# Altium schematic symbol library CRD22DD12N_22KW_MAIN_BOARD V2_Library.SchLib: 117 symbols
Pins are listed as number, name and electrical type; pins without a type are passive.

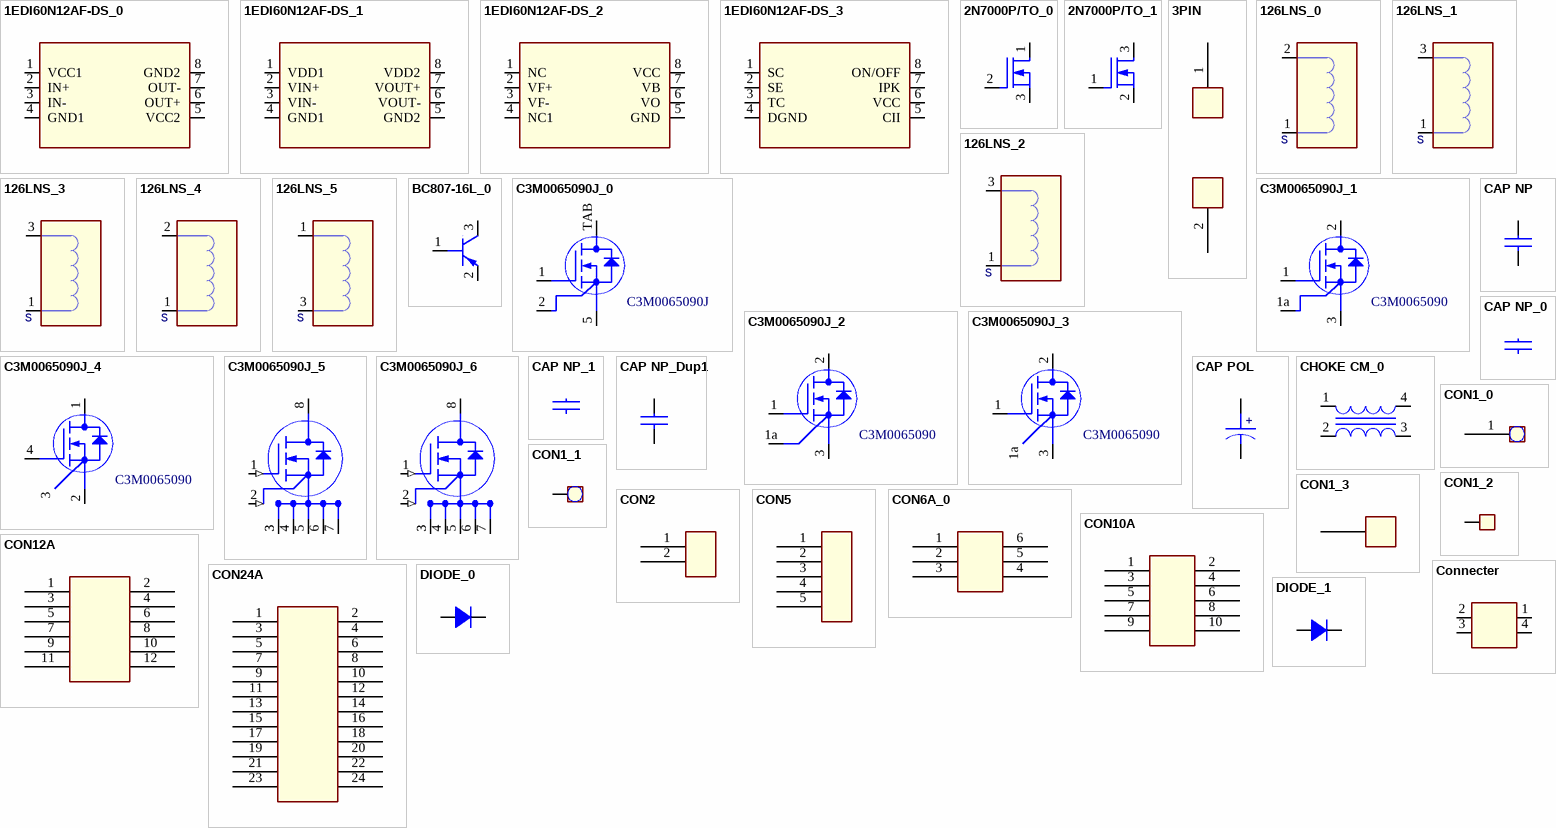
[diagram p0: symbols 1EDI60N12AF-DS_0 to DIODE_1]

## 1EDI60N12AF-DS_0
designator U?
pins: 1 VCC1, 2 IN+, 3 IN-, 4 GND1, 5 VCC2, 6 OUT+, 7 OUT-, 8 GND2

## 1EDI60N12AF-DS_1
designator U?
pins: 1 VDD1, 2 VIN+, 3 VIN-, 4 GND1, 5 GND2, 6 VOUT-, 7 VOUT+, 8 VDD2

## 1EDI60N12AF-DS_2
designator U?
pins: 1 NC, 2 VF+, 3 VF-, 4 NC1, 5 GND, 6 VO, 7 VB, 8 VCC

## 1EDI60N12AF-DS_3
designator U?
pins: 1 SC, 2 SE, 3 TC, 4 DGND, 5 CII, 6 VCC, 7 IPK, 8 ON/OFF

## 2N7000P/TO_0
designator Q?
pins: 1 D, 2 G, 3 S

## 2N7000P/TO_1
designator Q?
pins: 1 G, 2 S, 3 D

## 3PIN
designator CR?
pins: 1, 2

## 126LNS_0
designator L?
pins: 1, 2 3

## 126LNS_1
designator L?
pins: 1, 3

## 126LNS_2
designator L?
pins: 1, 3

## 126LNS_3
designator L?
pins: 1, 3

## 126LNS_4
designator L?
pins: 1, 2

## 126LNS_5
designator L?
pins: 1, 3

## BC807-16L_0
designator Q?
pins: 1 BASE, 2 EMITTER, 3 COLLECTOR

## C3M0065090J_0
designator Q?, comment C3M0065090J
pins: 1 G, 2 DS, 5 S3, TAB D

## C3M0065090J_1
designator Q?, comment C3M0065090
pins: 1 G, 1a DS, 2 D, 3 S

## C3M0065090J_2
designator Q?, comment C3M0065090
pins: 1 G, 1a DS, 2 D, 3 S

## C3M0065090J_3
designator Q?, comment C3M0065090
pins: 1 G, 1a DS, 2 D, 3 S

## C3M0065090J_4
designator Q?, comment C3M0065090
pins: 1 D, 2 S, 3 GS, 4 G

## C3M0065090J_5
designator Q?
pins: 1 GATE (in), 2 GATE RTN (in), 3 SOURCE, 3 SOURCE, 4 SOURCE4, 5 SOURCE5, 6 SOURCE6, 7 SOURCE7, 8 DRAIN

## C3M0065090J_6
designator Q?
pins: 1 GATE (in), 2 GATE RTN (in), 3 SOURCE, 3 SOURCE, 4 SOURCE4, 5 SOURCE5, 6 SOURCE6, 7 SOURCE7, 8 DRAIN

## CAP NP
designator C?
pins: 1, 2

## CAP NP_0
designator C?
pins: 1, 2

## CAP NP_1
designator C?
pins: 1, 2

## CAP NP_Dup1
designator C?
pins: 1, 2

## CAP POL
designator C?
pins: 1, 2

## CHOKE CM_0
designator L?
pins: 1, 2, 3, 4

## CON1_0
designator J?
pins: 1

## CON1_1
designator J?
pins: 1

## CON1_2
designator J?
pins: 1

## CON1_3
designator J?
pins: 1, 2, 3, 4

## CON2
designator J?
pins: 1, 2

## CON5
designator J?
pins: 1, 2, 3, 4, 5

## CON6A_0
designator J?
pins: 1, 2, 3, 4, 5, 6

## CON10A
designator J?
pins: 1, 2, 3, 4, 5, 6, 7, 8, 9, 10

## CON12A
designator J?
pins: 1, 2, 3, 4, 5, 6, 7, 8, 9, 10, 11, 12

## CON24A
designator J?
pins: 1, 2, 3, 4, 5, 6, 7, 8, 9, 10, 11, 12, 13, 14, 15, 16, 17, 18, 19, 20, 21, 22, 23, 24

## Connecter
designator CON?
pins: 1, 2, 3, 4

## DIODE_0
designator D?
pins: 1 A, 2 K

## DIODE_1
designator D?
pins: 1 K, 2 A

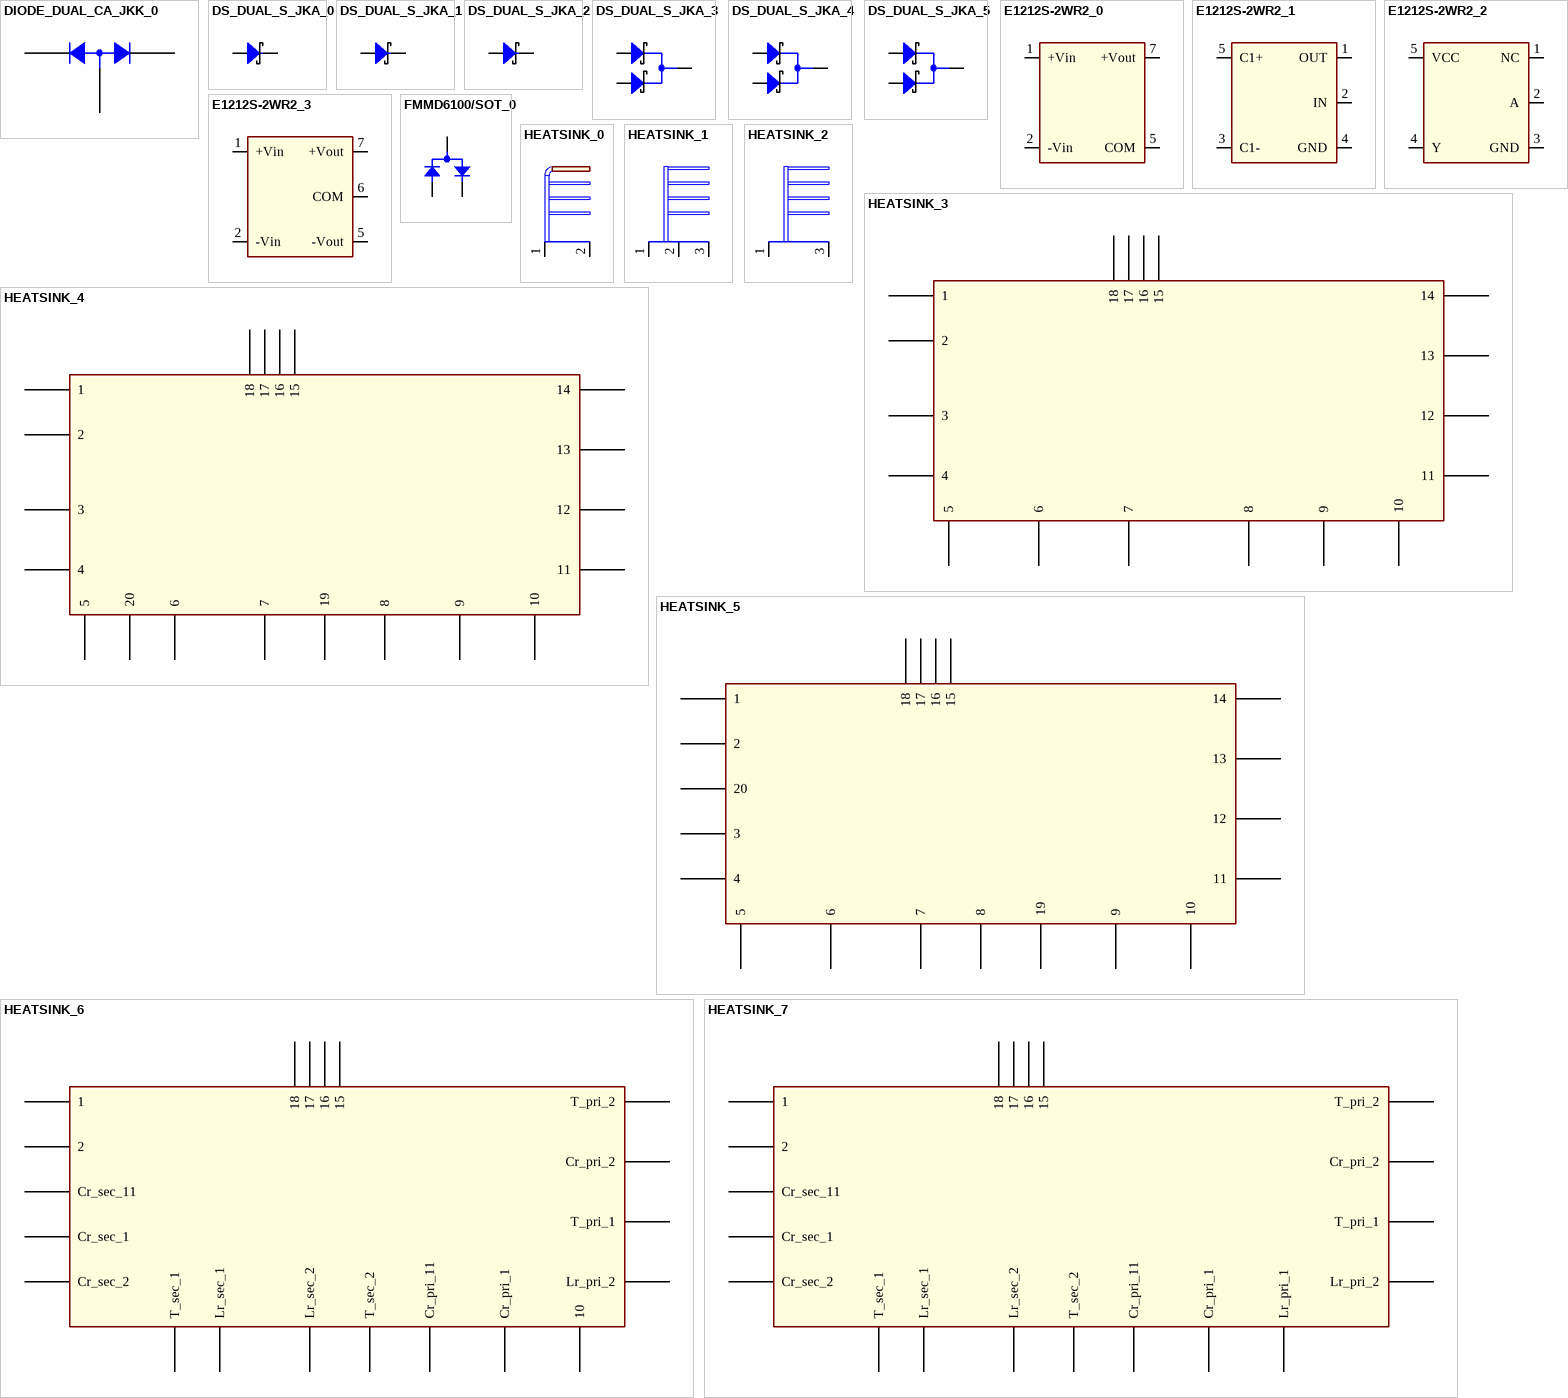
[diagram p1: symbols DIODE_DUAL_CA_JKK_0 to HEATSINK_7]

## DIODE_DUAL_CA_JKK_0
designator DN?
pins: 1 3, 2, 3 1

## DS_DUAL_S_JKA_0
designator DN?
pins: 1, 2

## DS_DUAL_S_JKA_1
designator DN?
pins: 1, 2

## DS_DUAL_S_JKA_2
designator DN?
pins: 1, 2

## DS_DUAL_S_JKA_3
designator DN?
pins: 1, 2, 3

## DS_DUAL_S_JKA_4
designator DN?
pins: 1, 2, 3

## DS_DUAL_S_JKA_5
designator DN?
pins: 1, 2, 3

## E1212S-2WR2_0
designator U?
pins: 1 +Vin, 2 -Vin, 5 COM, 7 +Vout

## E1212S-2WR2_1
designator U?
pins: 1 OUT, 2 IN, 3 C1-, 4 GND, 5 C1+

## E1212S-2WR2_2
designator U?
pins: 1 NC, 2 A, 3 GND, 4 Y, 5 VCC

## E1212S-2WR2_3
designator U?
pins: 1 +Vin, 2 -Vin, 5 -Vout, 6 COM, 7 +Vout

## FMMD6100/SOT_0
designator D?
pins: 1 C1, 2 C2, 3 A

## HEATSINK_0
designator HS?
pins: 1, 2

## HEATSINK_1
designator HS?
pins: 1, 2, 3

## HEATSINK_2
designator HS?
pins: 1, 3

## HEATSINK_3
designator T?
pins: 1, 2, 3, 4, 5, 6, 7, 8, 9, 10, 11, 12, 13, 14, 15, 16, 17, 18

## HEATSINK_4
designator T?
pins: 1, 2, 3, 4, 5, 6, 7, 8, 9, 10, 11, 12, 13, 14, 15, 16, 17, 18, 19, 20

## HEATSINK_5
designator T?
pins: 1, 2, 3, 4, 5, 6, 7, 8, 9, 10, 11, 12, 13, 14, 15, 16, 17, 18, 19, 20

## HEATSINK_6
designator T?
pins: 1, 2, 3 Cr_sec_1, 4 Cr_sec_2, 5 T_sec_1, 6 Lr_sec_1, 7 Lr_sec_2, 8 T_sec_2, 9 Cr_pri_1, 10, 11 Lr_pri_2, 12 T_pri_1, 13 Cr_pri_2, 14 T_pri_2, 15, 16, 17, 18, 19 Cr_pri_11, 20 Cr_sec_11

## HEATSINK_7
designator T?
pins: 1, 2, 3 Cr_sec_1, 4 Cr_sec_2, 5 T_sec_1, 6 Lr_sec_1, 7 Lr_sec_2, 8 T_sec_2, 9 Cr_pri_1, 10 Lr_pri_1, 11 Lr_pri_2, 12 T_pri_1, 13 Cr_pri_2, 14 T_pri_2, 15, 16, 17, 18, 19 Cr_pri_11, 20 Cr_sec_11

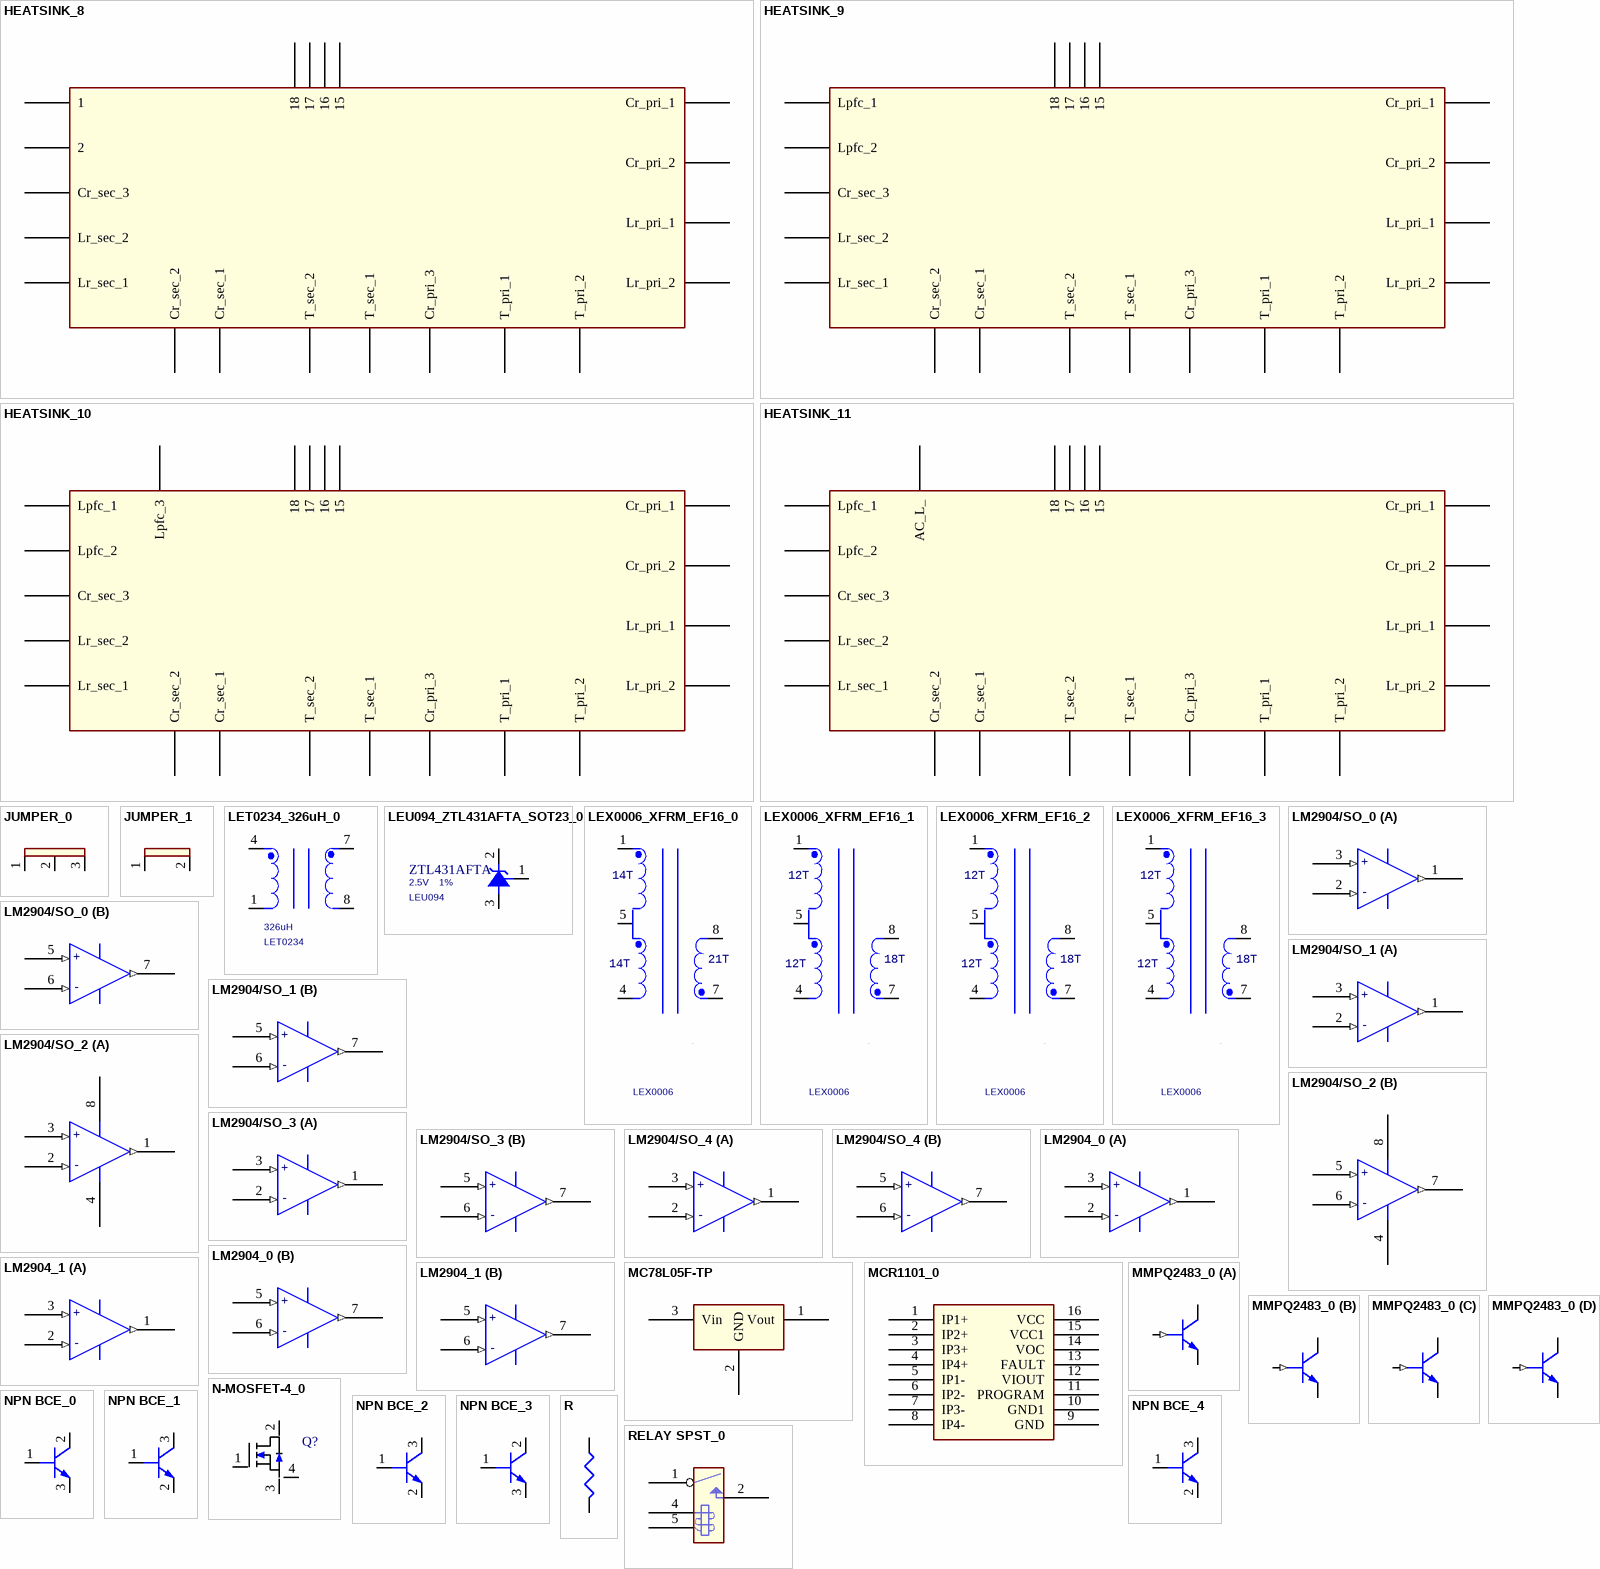
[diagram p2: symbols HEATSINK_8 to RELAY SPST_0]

## HEATSINK_8
designator T?
pins: 1, 2, 3 Lr_sec_2, 4 Lr_sec_1, 5 Cr_sec_2, 6 Cr_sec_1, 7 T_sec_2, 8 T_sec_1, 9 T_pri_1, 10 T_pri_2, 11 Lr_pri_2, 12 Lr_pri_1, 13 Cr_pri_2, 14 Cr_pri_1, 15, 16, 17, 18, 19 Cr_pri_3, 20 Cr_sec_3

## HEATSINK_9
designator T?
pins: 1 Lpfc_1, 2 Lpfc_2, 3 Lr_sec_2, 4 Lr_sec_1, 5 Cr_sec_2, 6 Cr_sec_1, 7 T_sec_2, 8 T_sec_1, 9 T_pri_1, 10 T_pri_2, 11 Lr_pri_2, 12 Lr_pri_1, 13 Cr_pri_2, 14 Cr_pri_1, 15, 16, 17, 18, 19 Cr_pri_3, 20 Cr_sec_3

## HEATSINK_10
designator T?
pins: 1 Lpfc_1, 2 Lpfc_2, 3 Lr_sec_2, 4 Lr_sec_1, 5 Cr_sec_2, 6 Cr_sec_1, 7 T_sec_2, 8 T_sec_1, 9 T_pri_1, 10 T_pri_2, 11 Lr_pri_2, 12 Lr_pri_1, 13 Cr_pri_2, 14 Cr_pri_1, 15, 16, 17, 18, 19 Cr_pri_3, 20 Cr_sec_3, 21 Lpfc_3

## HEATSINK_11
designator T?
pins: 1 Lpfc_1, 2 Lpfc_2, 3 Lr_sec_2, 4 Lr_sec_1, 5 Cr_sec_2, 6 Cr_sec_1, 7 T_sec_2, 8 T_sec_1, 9 T_pri_1, 10 T_pri_2, 11 Lr_pri_2, 12 Lr_pri_1, 13 Cr_pri_2, 14 Cr_pri_1, 15, 16, 17, 18, 19 Cr_pri_3, 20 Cr_sec_3, 21 AC_L_

## JUMPER_0
designator JM?
pins: 1, 2, 3

## JUMPER_1
designator JM?
pins: 1, 2

## LET0234_326uH_0
designator T?, comment 326uH  LLF Part Number: LET0234
footprint IND-LET0234-34x17
pins: 1, 4, 7, 8

## LEU094_ZTL431AFTA_SOT23_0
designator U?, comment ZTL431AFTA  VREF: 2.5V  Tolerance: 1%  LLF Part Number: LEU094
footprint SOT23_1-32
pins: 1 REF, 2 K, 3 A

## LEX0006_XFRM_EF16_0
designator T?, comment LLF Part Number: LEX0006  (hidden comment: 8.5mH)
NC: 2,3,5,6,7
footprint XFMR-EF16-v
pins: 1, 4, 5, 7, 8

## LEX0006_XFRM_EF16_1
designator T?, comment LLF Part Number: LEX0006  (hidden comment: 8.5mH)
NC: 2,3,5,6,7
footprint XFMR-EF16-v
pins: 1, 4, 5, 7, 8

## LEX0006_XFRM_EF16_2
designator T?, comment LLF Part Number: LEX0006  (hidden comment: 8.5mH)
NC: 2,3,5,6,7
footprint XFMR-EF16-v
pins: 1, 4, 5, 7, 8

## LEX0006_XFRM_EF16_3
designator T?, comment LLF Part Number: LEX0006  (hidden comment: 8.5mH)
footprint XFMR-EF16-v
pins: 1, 4, 5, 7, 8

## LM2904/SO_0
designator U?
part A pins: 1 OUT (out), 2 -IN (in), 3 +IN (in)
part B pins: 5 +IN (in), 6 -IN (in), 7 OUT (out)

## LM2904/SO_1
designator U?
part A pins: 1 OUT (out), 2 -IN (in), 3 +IN (in)
part B pins: 5 +IN (in), 6 -IN (in), 7 OUT (out)

## LM2904/SO_2
designator U?
part A pins: 1 OUT (out), 2 -IN (in), 3 +IN (in), 4 V- (power), 8 V+ (power)
part B pins: 4 V- (power), 5 +IN (in), 6 -IN (in), 7 OUT (out), 8 V+ (power)

## LM2904/SO_3
designator U?
part A pins: 1 OUT (out), 2 -IN (in), 3 +IN (in), 4 V- (power) hidden, 8 V+ (power) hidden
part B pins: 4 V- (power) hidden, 5 +IN (in), 6 -IN (in), 7 OUT (out), 8 V+ (power) hidden

## LM2904/SO_4
designator U?
part A pins: 1 OUT (out), 2 -IN (in), 3 +IN (in), 4 V- (power) hidden, 8 V+ (power) hidden
part B pins: 4 V- (power) hidden, 5 +IN (in), 6 -IN (in), 7 OUT (out), 8 V+ (power) hidden

## LM2904_0
designator U?
part A pins: 1 OUT (out), 2 -IN (in), 3 +IN (in)
part B pins: 5 +IN (in), 6 -IN (in), 7 OUT (out)

## LM2904_1
designator U?
part A pins: 1 OUT (out), 2 -IN (in), 3 +IN (in), 4 V- (power) hidden, 8 V+ (power) hidden
part B pins: 4 V- (power) hidden, 5 +IN (in), 6 -IN (in), 7 OUT (out), 8 V+ (power) hidden

## MC78L05F-TP
designator U?
pins: 1 Vout, 2 GND, 3 Vin

## MCR1101_0
designator U?
pins: 1 IP1+, 2 IP2+, 3 IP3+, 4 IP4+, 5 IP1-, 6 IP2-, 7 IP3-, 8 IP4-, 9 GND, 10 GND1, 11 PROGRAM, 12 VIOUT, 13 FAULT, 14 VOC, 15 VCC1, 16 VCC

## MMPQ2483_0
designator Q?
part A pins: 1 B (in), 2 E, 3 C
part B pins: 5 E, 6 B (in), 7 C
part C pins: 8 C, 9 B (in), 10 E
part D pins: 12 E, 13 B (in), 14 C

## N-MOSFET-4_0
designator Q?  (value not drawn)
footprint TO-247-4
pins: 1 G, 2 D, 3 S1, 4 S

## NPN BCE_0
designator Q?
PspiceTemplate: Q^@REFDES %C %B %E
simulation model NPN BCE_0
pins: 1 B, 2 C, 3 E

## NPN BCE_1
designator Q?
PspiceTemplate: Q^@REFDES %C %B %E
simulation model NPN BCE_1
pins: 1 B, 2 E, 3 C

## NPN BCE_2
designator Q?
PspiceTemplate: Q^@REFDES %C %B %E
simulation model NPN BCE_2
pins: 1 B, 2 E, 3 C

## NPN BCE_3
designator Q?
PspiceTemplate: Q^@REFDES %C %B %E
simulation model NPN BCE_3
pins: 1 B, 2 C, 3 E

## NPN BCE_4
designator Q?
PspiceTemplate: Q^@REFDES %C %B %E
simulation model NPN BCE_4
pins: 1 B, 2 E, 3 C

## R
designator R?
pins: 1, 2

## RELAY SPST_0
designator RL?
pins: 1 COMMON, 2 NO, 4 COIL1, 5 COIL2

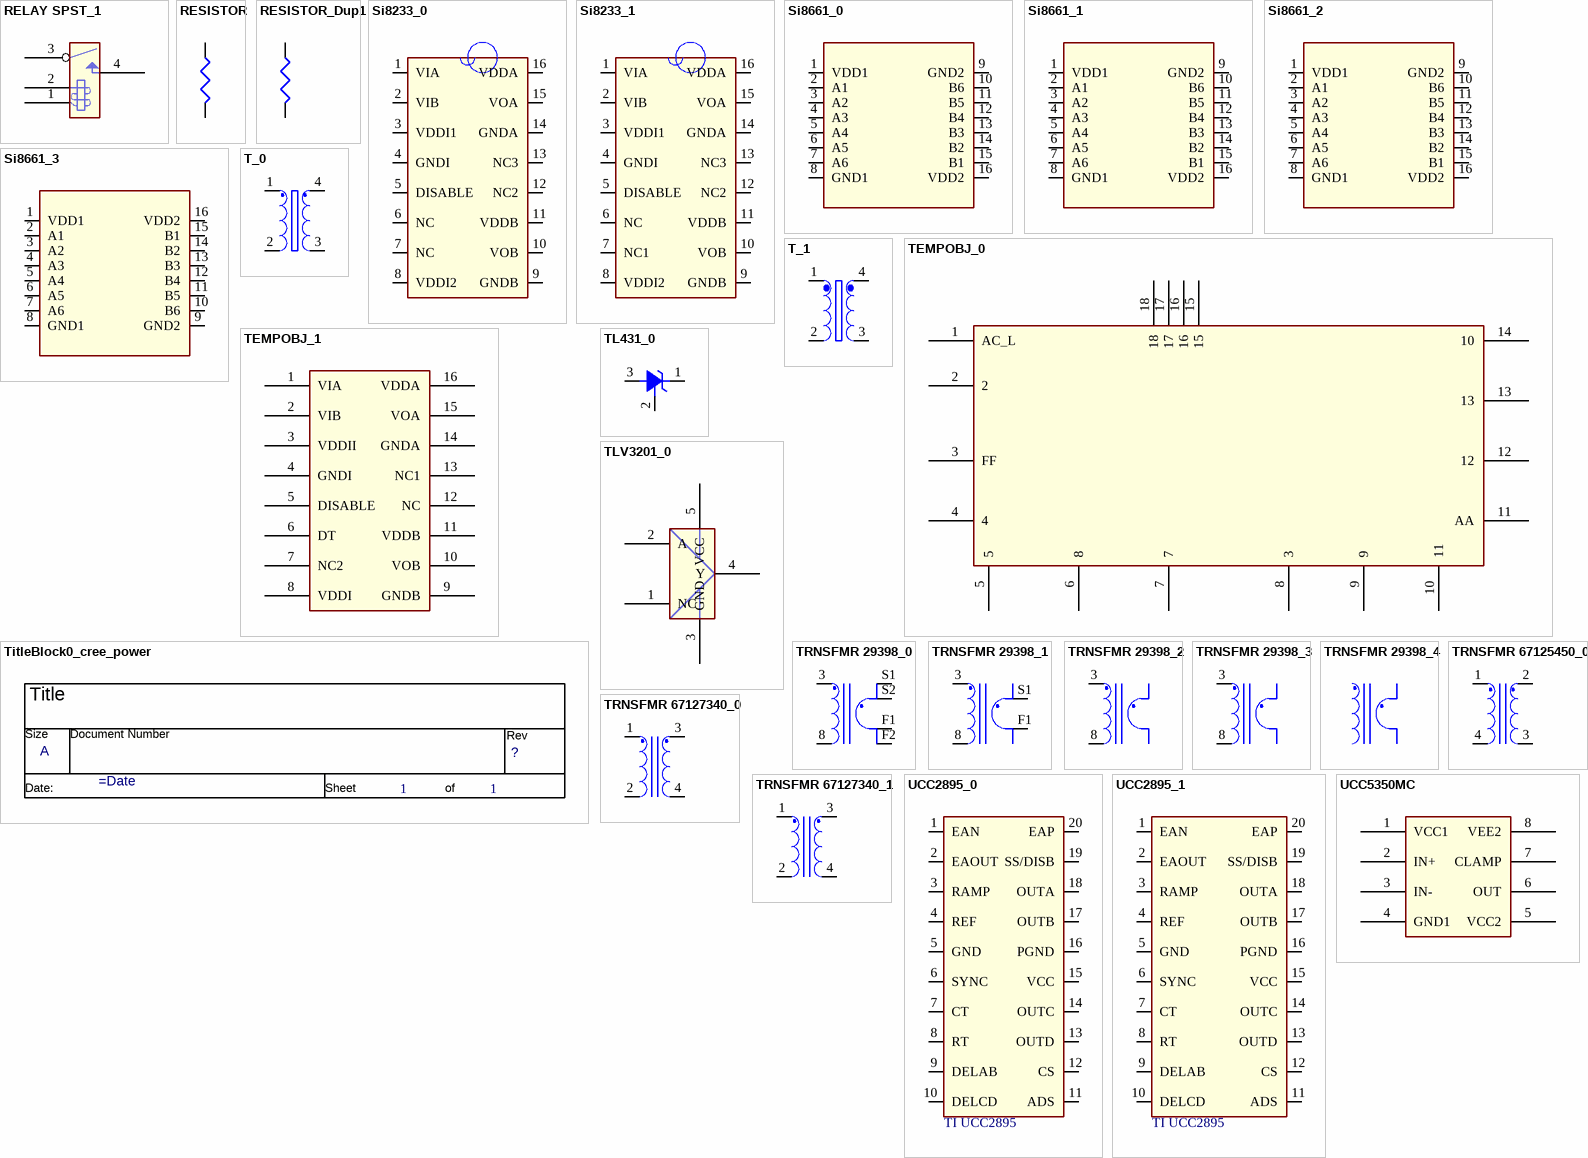
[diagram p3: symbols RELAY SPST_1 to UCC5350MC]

## RELAY SPST_1
designator RL?
pins: 1 COIL2, 2 COIL1, 3 COMMON, 4 NO

## RESISTOR
designator R?
pins: 1, 2

## RESISTOR_Dup1
designator R?
pins: 1, 2

## Si8233_0
designator U?
pins: 1 VIA, 2 VIB, 3 VDDI1, 4 GNDI, 5 DISABLE, 6 NC, 7 NC, 8 VDDI2, 9 GNDB, 10 VOB, 11 VDDB, 12 NC2, 13 NC3, 14 GNDA, 15 VOA, 16 VDDA

## Si8233_1
designator U?
pins: 1 VIA, 2 VIB, 3 VDDI1, 4 GNDI, 5 DISABLE, 6 NC, 7 NC1, 8 VDDI2, 9 GNDB, 10 VOB, 11 VDDB, 12 NC2, 13 NC3, 14 GNDA, 15 VOA, 16 VDDA

## Si8661_0
designator U?
pins: 1 VDD1, 2 A1, 3 A2, 4 A3, 5 A4, 6 A5, 7 A6, 8 GND1, 9 GND2, 10 B6, 11 B5, 12 B4, 13 B3, 14 B2, 15 B1, 16 VDD2

## Si8661_1
designator U?
pins: 1 VDD1, 2 A1, 3 A2, 4 A3, 5 A4, 6 A5, 7 A6, 8 GND1, 9 GND2, 10 B6, 11 B5, 12 B4, 13 B3, 14 B2, 15 B1, 16 VDD2

## Si8661_2
designator U?
pins: 1 VDD1, 2 A1, 3 A2, 4 A3, 5 A4, 6 A5, 7 A6, 8 GND1, 9 GND2, 10 B6, 11 B5, 12 B4, 13 B3, 14 B2, 15 B1, 16 VDD2

## Si8661_3
designator U?
pins: 1 VDD1, 2 A1, 3 A2, 4 A3, 5 A4, 6 A5, 7 A6, 8 GND1, 9 GND2, 10 B6, 11 B5, 12 B4, 13 B3, 14 B2, 15 B1, 16 VDD2

## T_0
designator T?
pins: 1, 2, 3, 4

## T_1
designator T?
pins: 1, 2, 3, 4

## TEMPOBJ_0
designator T?
pins: 1 AC_L, 2, 3 FF, 4, 5, 6 8, 7, 8 3, 9, 10 11, 11 AA, 12, 13, 14 10, 15, 16, 17, 18

## TEMPOBJ_1
designator U?
pins: 1 VIA, 2 VIB, 3 VDDII, 4 GNDI, 5 DISABLE, 6 DT, 7 NC2, 8 VDDI, 9 GNDB, 10 VOB, 11 VDDB, 12 NC, 13 NC1, 14 GNDA, 15 VOA, 16 VDDA

## TitleBlock0_cree_power
designator *  Page Count: 1  Page Size: A  (hidden comment: *)  (graphical)

## TL431_0
designator U?
pins: 1 K, 2 REF, 3 A

## TLV3201_0
designator U?
pins: 1 NC, 2 A, 3 GND, 4 Y, 5 VCC

## TRNSFMR 29398_0
designator T?
pins: 3 P1, 8 P2, F1 S12, F2 S22, S1 S11, S2 S21

## TRNSFMR 29398_1
designator T?
pins: 3 P1, 8 P2, F1 S12, S1 S11

## TRNSFMR 29398_2
designator T?
pins: 3 P1, 8 P2

## TRNSFMR 29398_3
designator T?
pins: 3 P1, 8 P2

## TRNSFMR 29398_4
designator T?

## TRNSFMR 67125450_0
designator T?
pins: 1 P11, 2 P21, 3 P22, 4 P12

## TRNSFMR 67127340_0
designator T?
pins: 1 P1, 2 P2, 3 S1, 4 S2

## TRNSFMR 67127340_1
designator T?
pins: 1 P1, 2 P2, 3 S1, 4 S2

## UCC2895_0
designator U?, comment TI UCC2895
pins: 1 EAN, 2 EAOUT, 3 RAMP, 4 REF, 5 GND, 6 SYNC, 7 CT, 8 RT, 9 DELAB, 10 DELCD, 11 ADS, 12 CS, 13 OUTD, 14 OUTC, 15 VCC, 16 PGND, 17 OUTB, 18 OUTA, 19 SS/DISB, 20 EAP

## UCC2895_1
designator U?, comment TI UCC2895
pins: 1 EAN, 2 EAOUT, 3 RAMP, 4 REF, 5 GND, 6 SYNC, 7 CT, 8 RT, 9 DELAB, 10 DELCD, 11 ADS, 12 CS, 13 OUTD, 14 OUTC, 15 VCC, 16 PGND, 17 OUTB, 18 OUTA, 19 SS/DISB, 20 EAP

## UCC5350MC
designator U?
pins: 1 VCC1, 2 IN+, 3 IN-, 4 GND1, 5 VCC2, 6 OUT, 7 CLAMP, 8 VEE2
